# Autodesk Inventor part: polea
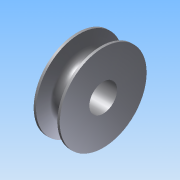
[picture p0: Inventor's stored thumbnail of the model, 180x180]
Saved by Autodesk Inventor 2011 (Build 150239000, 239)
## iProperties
Created: 2020-12
Part Number: polea
Document SubType Name: Modeling
Designer: PC
Density: 1 g/cm^3
Author: PC
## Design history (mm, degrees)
sketch "Sketch1"
  geometry: L1 (0, 0)-(0, 140.75); L2 (7.5, 25)-(7.5, 0); L3 (7.5, 0)-(-7.5, 0); L4 (-7.5, 0)-(-7.5, 25); L5 (-6.135, 25)-(-4.924, 18.132); L6 (6.135, 25)-(4.924, 18.132); L7 (-7.5, 25)-(-6.135, 25); L8 (6.135, 25)-(7.5, 25); L9 (-10.5, 0)-(10.5, 0) reference; A1 r 5 centre (0, 19) between (-4.924, 18.132) and (4.924, 18.132)
  constraints: 16 end point, 3 parallel, 2 horizontal, 2 perpendicular, 2 point on circle, 2 symmetric about line, 1 centre point, 1 midpoint, 1 point on line, 1 tangent, 1 vertical
  dimensions: "d0" = 10 diameter of A1; "d1" = 15 distance between parallel lines of L2 L4; "d3" = 6 distance from line of L7 A1.centre (= 0.6 x d0); "d4" = 20 deg angle of L6 L5; "d5" = 25 distance between parallel lines of L7 L3
revolve "Revolution1" sketch "Sketch1" stored, may be unused: angle "d6" = 90 deg
hole "Hole1" diameter "d9" = 16; stored, may be unused: countersink angle "d13" = 90 deg, drill point angle "d15" = 118 deg; dims "d7" = 10, "d8" = 10, "d10" = 6, "d11" = 4, "d12" = 2, "d14" = 8
body "Solid1"
other parameters: "d2" = 6 (= 0.6 x d0)
